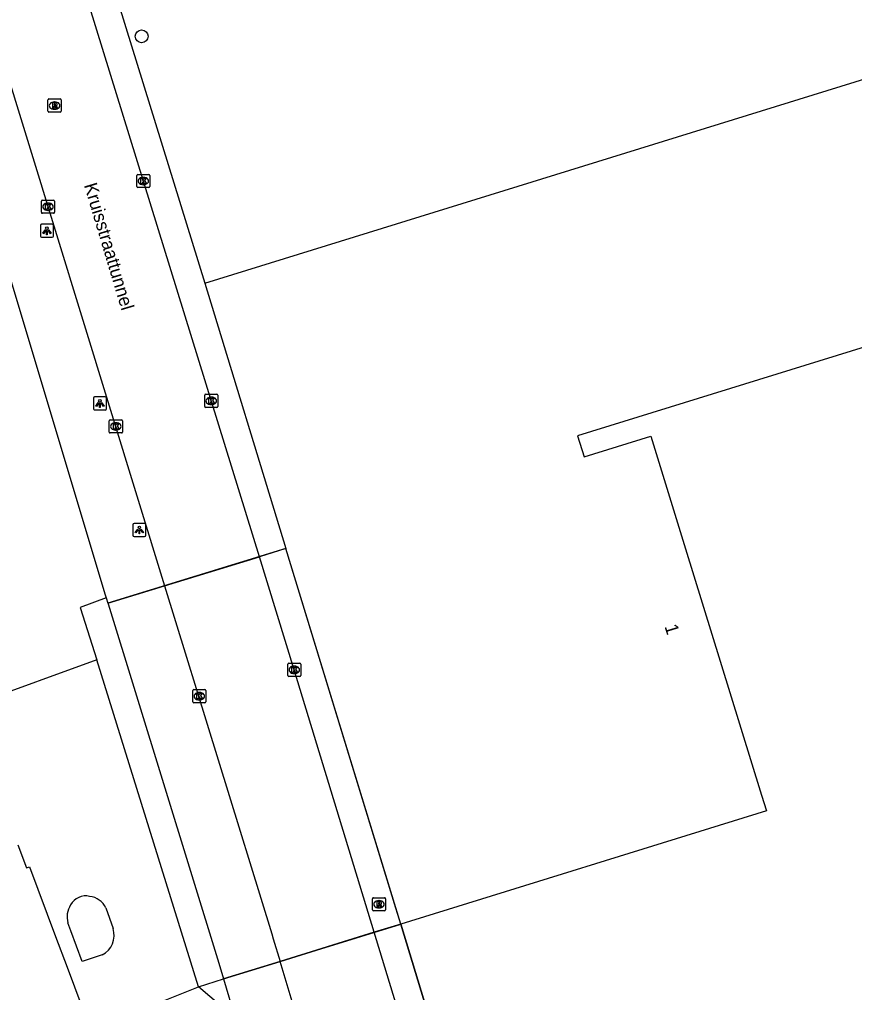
# Model space of a CAD drawing. Extents: x 160806 to 161707, y 383697 to 384148.
# Drawn here: x 161101 to 161164.6, y 383921.8 to 383995.8 of the extents above; entities that cross this region are included whole.
import ezdxf

# ---------------------------------------------------------------- set-up
doc = ezdxf.new("R2010")
doc.units = 0
for name, color, linetype in [('IMGEO_Boom', 7, 'Continuous'), ('IMGEO_Erf', 7, 'Continuous'), ('IMGEO_Fietspad_gesloten', 7, 'Continuous'), ('IMGEO_Kolk', 7, 'Continuous'), ('IMGEO_Lichtpunt', 7, 'Continuous'), ('IMGEO_Muur', 7, 'Continuous'), ('IMGEO_Openbare_ruimte_label', 7, 'Continuous'), ('IMGEO_Pand', 7, 'Continuous'), ('IMGEO_Pand_nummerreeks', 7, 'Continuous'), ('IMGEO_Pand_overbouw', 7, 'Continuous'), ('IMGEO_Rioolput', 7, 'Continuous'), ('IMGEO_Tunneldeel', 7, 'Continuous'), ('IMGEO_Voetpad_open', 7, 'Continuous')]:
    doc.layers.add(name, color=color, linetype=linetype)

msp = doc.modelspace()

# ---------------------------------------------------------------- linework, layer by layer
at = {"layer": 'IMGEO_Boom'}
msp.add_circle((161110.294, 383994.548), 0.489, dxfattribs=at)
at = {"layer": 'IMGEO_Erf'}
msp.add_lwpolyline([(161130.022, 383926.988), (161135.107, 383910.27)], dxfattribs=at)
at = {"layer": 'IMGEO_Fietspad_gesloten'}
for points in [[(161119.258, 383954.945), (161104.758, 384001.93), (161103.731, 384005.273), (161103.627, 384007.38)], [(161096.658, 384002.717), (161097.481, 384000.05), (161112.041, 383952.737)], [(161112.041, 383952.737), (161119.258, 383954.945)], [(161128.001, 383926.363), (161121.915, 383946.336), (161119.258, 383954.945)], [(161112.041, 383952.737), (161120.194, 383926.245), (161120.308, 383925.869), (161120.828, 383924.144)], [(161120.828, 383924.144), (161128.001, 383926.363)], [(161128.001, 383926.363), (161120.828, 383924.144)], [(161137.527, 383894.886), (161137.397, 383895.319), (161137.082, 383896.366), (161136.2, 383899.301), (161135.228, 383902.537), (161134.295, 383905.64), (161133.125, 383909.533), (161132.871, 383910.379), (161128.001, 383926.363)], [(161130.415, 383892.303), (161130.285, 383892.737), (161129.981, 383893.745), (161129.099, 383896.676), (161128.124, 383899.912), (161127.188, 383903.021), (161124.879, 383910.69), (161120.828, 383924.144)]]:
    msp.add_lwpolyline(points, dxfattribs=at)
at = {"layer": 'IMGEO_Kolk'}
for p, q in [((161109.919, 383983.109), (161109.919, 383983.961)), ((161109.994, 383984.035), (161110.846, 383984.035)), ((161110.407, 383983.815), (161110.432, 383983.815)), ((161110.92, 383983.961), (161110.92, 383983.109)), ((161110.846, 383983.035), (161109.994, 383983.035)), ((161110.43, 383983.255), (161110.405, 383983.255)), ((161102.662, 383981.155), (161102.662, 383982.007)), ((161102.737, 383982.081), (161103.589, 383982.081)), ((161103.15, 383981.861), (161103.175, 383981.861)), ((161103.663, 383982.007), (161103.663, 383981.155)), ((161103.589, 383981.081), (161102.737, 383981.081)), ((161103.173, 383981.301), (161103.148, 383981.301)), ((161115.168, 383967.306), (161116.02, 383967.306)), ((161115.093, 383966.38), (161115.093, 383967.232)), ((161115.581, 383967.086), (161115.606, 383967.086)), ((161116.094, 383967.232), (161116.094, 383966.38)), ((161116.02, 383966.306), (161115.168, 383966.306)), ((161115.604, 383966.526), (161115.579, 383966.526)), ((161107.828, 383964.435), (161107.828, 383965.287)), ((161107.903, 383965.361), (161108.755, 383965.361)), ((161108.316, 383965.141), (161108.341, 383965.141)), ((161108.829, 383965.287), (161108.829, 383964.435)), ((161108.755, 383964.361), (161107.903, 383964.361)), ((161108.339, 383964.581), (161108.314, 383964.581)), ((161121.414, 383945.91), (161121.414, 383946.762)), ((161121.489, 383946.836), (161122.341, 383946.836)), ((161121.902, 383946.616), (161121.927, 383946.616)), ((161122.415, 383946.762), (161122.415, 383945.91)), ((161122.341, 383945.836), (161121.489, 383945.836)), ((161121.925, 383946.056), (161121.9, 383946.056)), ((161114.183, 383943.904), (161114.183, 383944.756)), ((161114.258, 383944.83), (161115.11, 383944.83)), ((161114.671, 383944.61), (161114.696, 383944.61)), ((161115.184, 383944.756), (161115.184, 383943.904)), ((161115.11, 383943.83), (161114.258, 383943.83)), ((161114.694, 383944.05), (161114.669, 383944.05))]:
    msp.add_line(p, q, dxfattribs=at)
for points in [[(161109.919, 383983.109), (161109.919, 383983.961)], [(161109.994, 383984.035), (161110.846, 383984.035)], [(161110.24, 383983.735), (161110.363, 383983.735), (161110.363, 383983.584), (161110.493, 383983.735), (161110.657, 383983.735), (161110.511, 383983.584), (161110.664, 383983.335), (161110.512, 383983.335), (161110.427, 383983.499), (161110.363, 383983.432), (161110.363, 383983.335), (161110.24, 383983.335), (161110.24, 383983.735)], [(161110.92, 383983.961), (161110.92, 383983.109)], [(161110.846, 383983.035), (161109.994, 383983.035)], [(161102.662, 383981.155), (161102.662, 383982.007)], [(161102.737, 383982.081), (161103.589, 383982.081)], [(161102.983, 383981.781), (161103.106, 383981.781), (161103.106, 383981.63), (161103.236, 383981.781), (161103.4, 383981.781), (161103.254, 383981.63), (161103.407, 383981.381), (161103.255, 383981.381), (161103.17, 383981.545), (161103.106, 383981.478), (161103.106, 383981.381), (161102.983, 383981.381), (161102.983, 383981.781)], [(161103.663, 383982.007), (161103.663, 383981.155)], [(161103.589, 383981.081), (161102.737, 383981.081)], [(161115.168, 383967.306), (161116.02, 383967.306)], [(161115.093, 383966.38), (161115.093, 383967.232)], [(161115.414, 383967.006), (161115.537, 383967.006), (161115.537, 383966.855), (161115.667, 383967.006), (161115.831, 383967.006), (161115.685, 383966.855), (161115.838, 383966.606), (161115.686, 383966.606), (161115.601, 383966.77), (161115.537, 383966.703), (161115.537, 383966.606), (161115.414, 383966.606), (161115.414, 383967.006)], [(161116.094, 383967.232), (161116.094, 383966.38)], [(161116.02, 383966.306), (161115.168, 383966.306)], [(161107.828, 383964.435), (161107.828, 383965.287)], [(161107.903, 383965.361), (161108.755, 383965.361)], [(161108.149, 383965.061), (161108.272, 383965.061), (161108.272, 383964.91), (161108.402, 383965.061), (161108.566, 383965.061), (161108.42, 383964.91), (161108.573, 383964.661), (161108.421, 383964.661), (161108.336, 383964.825), (161108.272, 383964.758), (161108.272, 383964.661), (161108.149, 383964.661), (161108.149, 383965.061)], [(161108.829, 383965.287), (161108.829, 383964.435)], [(161108.755, 383964.361), (161107.903, 383964.361)], [(161121.414, 383945.91), (161121.414, 383946.762)], [(161121.489, 383946.836), (161122.341, 383946.836)], [(161122.415, 383946.762), (161122.415, 383945.91)], [(161122.341, 383945.836), (161121.489, 383945.836)], [(161121.735, 383946.536), (161121.858, 383946.536), (161121.858, 383946.385), (161121.988, 383946.536), (161122.152, 383946.536), (161122.006, 383946.385), (161122.159, 383946.136), (161122.007, 383946.136), (161121.922, 383946.3), (161121.858, 383946.233), (161121.858, 383946.136), (161121.735, 383946.136), (161121.735, 383946.536)], [(161114.183, 383943.904), (161114.183, 383944.756)], [(161114.258, 383944.83), (161115.11, 383944.83)], [(161114.504, 383944.53), (161114.627, 383944.53), (161114.627, 383944.379), (161114.757, 383944.53), (161114.921, 383944.53), (161114.775, 383944.379), (161114.928, 383944.13), (161114.776, 383944.13), (161114.691, 383944.294), (161114.627, 383944.227), (161114.627, 383944.13), (161114.504, 383944.13), (161114.504, 383944.53)], [(161115.184, 383944.756), (161115.184, 383943.904)], [(161115.11, 383943.83), (161114.258, 383943.83)]]:
    msp.add_lwpolyline(points, dxfattribs=at)
for centre, start, end in [((161109.996, 383983.959), 91.55205, 178.44795), ((161109.996, 383983.959), 91.55205, 178.44795), ((161110.844, 383983.959), 1.55205, 88.44795), ((161110.844, 383983.959), 1.55205, 88.44795), ((161109.996, 383983.111), 181.55205, 268.44795), ((161109.996, 383983.111), 181.55205, 268.44795), ((161110.844, 383983.111), 271.55205, 358.44795), ((161110.844, 383983.111), 271.55205, 358.44795), ((161102.739, 383982.005), 91.55205, 178.44795), ((161102.739, 383982.005), 91.55205, 178.44795), ((161103.587, 383982.005), 1.55205, 88.44795), ((161103.587, 383982.005), 1.55205, 88.44795), ((161102.739, 383981.157), 181.55205, 268.44795), ((161102.739, 383981.157), 181.55205, 268.44795), ((161103.587, 383981.157), 271.55205, 358.44795), ((161103.587, 383981.157), 271.55205, 358.44795), ((161115.17, 383967.23), 91.55205, 178.44795), ((161115.17, 383967.23), 91.55205, 178.44795), ((161116.018, 383967.23), 1.55205, 88.44795), ((161116.018, 383967.23), 1.55205, 88.44795), ((161115.17, 383966.382), 181.55205, 268.44795), ((161115.17, 383966.382), 181.55205, 268.44795), ((161116.018, 383966.382), 271.55205, 358.44795), ((161116.018, 383966.382), 271.55205, 358.44795), ((161107.905, 383965.285), 91.55205, 178.44795), ((161107.905, 383965.285), 91.55205, 178.44795), ((161108.753, 383965.285), 1.55205, 88.44795), ((161108.753, 383965.285), 1.55205, 88.44795), ((161107.905, 383964.437), 181.55205, 268.44795), ((161107.905, 383964.437), 181.55205, 268.44795), ((161108.753, 383964.437), 271.55205, 358.44795), ((161108.753, 383964.437), 271.55205, 358.44795), ((161121.491, 383946.76), 91.55205, 178.44795), ((161121.491, 383946.76), 91.55205, 178.44795), ((161122.339, 383946.76), 1.55205, 88.44795), ((161122.339, 383946.76), 1.55205, 88.44795), ((161121.491, 383945.912), 181.55205, 268.44795), ((161121.491, 383945.912), 181.55205, 268.44795), ((161122.339, 383945.912), 271.55205, 358.44795), ((161122.339, 383945.912), 271.55205, 358.44795), ((161114.26, 383944.754), 91.55205, 178.44795), ((161114.26, 383944.754), 91.55205, 178.44795), ((161115.108, 383944.754), 1.55205, 88.44795), ((161115.108, 383944.754), 1.55205, 88.44795), ((161114.26, 383943.906), 181.55205, 268.44795), ((161114.26, 383943.906), 181.55205, 268.44795), ((161115.108, 383943.906), 271.55205, 358.44795), ((161115.108, 383943.906), 271.55205, 358.44795)]:
    msp.add_arc(centre, 0.0765, start, end, dxfattribs=at)
for centre, major_axis, ratio, start_param, end_param in [((161110.406, 383983.535), (-0.387, 0.002), 0.722429, 4.712389, 7.853982), ((161110.431, 383983.535), (-0.39, 0.002), 0.717154, 1.570796, 4.712389), ((161103.149, 383981.581), (-0.387, 0.002), 0.722429, 4.712389, 7.853982), ((161103.174, 383981.581), (-0.39, 0.002), 0.717154, 1.570796, 4.712389), ((161115.58, 383966.806), (-0.387, 0.002), 0.722429, 4.712389, 7.853982), ((161115.605, 383966.806), (-0.39, 0.002), 0.717154, 1.570796, 4.712389), ((161108.315, 383964.861), (-0.387, 0.002), 0.722429, 4.712389, 7.853982), ((161108.34, 383964.861), (-0.39, 0.002), 0.717154, 1.570796, 4.712389), ((161121.901, 383946.336), (-0.387, 0.002), 0.722429, 4.712389, 7.853982), ((161121.926, 383946.336), (-0.39, 0.002), 0.717154, 1.570796, 4.712389), ((161114.67, 383944.33), (-0.387, 0.002), 0.722429, 4.712389, 7.853982), ((161114.695, 383944.33), (-0.39, 0.002), 0.717154, 1.570796, 4.712389)]:
    msp.add_ellipse(centre, major_axis=major_axis, ratio=ratio, start_param=start_param, end_param=end_param, dxfattribs=at)
at = {"layer": 'IMGEO_Lichtpunt'}
for p, q in [((161102.588, 383980.156), (161102.588, 383979.349)), ((161102.588, 383980.156), (161102.588, 383979.349)), ((161103.49, 383980.251), (161102.682, 383980.251)), ((161103.49, 383980.251), (161102.682, 383980.251)), ((161103.584, 383979.349), (161103.584, 383980.156)), ((161103.584, 383979.349), (161103.584, 383980.156)), ((161102.682, 383979.255), (161103.49, 383979.255)), ((161102.682, 383979.255), (161103.49, 383979.255)), ((161106.623, 383967.012), (161106.623, 383966.205)), ((161106.623, 383967.012), (161106.623, 383966.205)), ((161107.525, 383967.107), (161106.717, 383967.107)), ((161107.525, 383967.107), (161106.717, 383967.107)), ((161107.619, 383966.205), (161107.619, 383967.012)), ((161107.619, 383966.205), (161107.619, 383967.012)), ((161106.717, 383966.111), (161107.525, 383966.111)), ((161106.717, 383966.111), (161107.525, 383966.111)), ((161109.621, 383957.381), (161109.621, 383956.574)), ((161109.621, 383957.381), (161109.621, 383956.574)), ((161110.523, 383957.476), (161109.715, 383957.476)), ((161110.523, 383957.476), (161109.715, 383957.476)), ((161110.617, 383956.574), (161110.617, 383957.381)), ((161110.617, 383956.574), (161110.617, 383957.381)), ((161109.715, 383956.48), (161110.523, 383956.48)), ((161109.715, 383956.48), (161110.523, 383956.48))]:
    msp.add_line(p, q, dxfattribs=at)
for points in [[(161102.962, 383979.82), (161103.001, 383979.792), (161102.813, 383979.53), (161102.775, 383979.557), (161102.962, 383979.82)], [(161103.064, 383979.772), (161103.111, 383979.772), (161103.111, 383979.45), (161103.064, 383979.45), (161103.064, 383979.772)], [(161103.174, 383979.792), (161103.212, 383979.819), (161103.399, 383979.557), (161103.36, 383979.529), (161103.174, 383979.792)], [(161106.997, 383966.676), (161107.036, 383966.648), (161106.848, 383966.386), (161106.81, 383966.413), (161106.997, 383966.676)], [(161107.099, 383966.628), (161107.146, 383966.628), (161107.146, 383966.306), (161107.099, 383966.306), (161107.099, 383966.628)], [(161107.209, 383966.648), (161107.247, 383966.675), (161107.434, 383966.413), (161107.395, 383966.385), (161107.209, 383966.648)], [(161109.995, 383957.045), (161110.034, 383957.017), (161109.846, 383956.755), (161109.808, 383956.782), (161109.995, 383957.045)], [(161110.097, 383956.997), (161110.144, 383956.997), (161110.144, 383956.675), (161110.097, 383956.675), (161110.097, 383956.997)], [(161110.207, 383957.017), (161110.245, 383957.044), (161110.432, 383956.782), (161110.393, 383956.754), (161110.207, 383957.017)]]:
    msp.add_lwpolyline(points, dxfattribs=at)
for centre in [(161103.087, 383979.954), (161107.122, 383966.81), (161110.12, 383957.179)]:
    msp.add_circle(centre, 0.0994, dxfattribs=at)
for centre, start, end in [((161102.682, 383980.156), 90, 180), ((161102.682, 383980.156), 90, 180), ((161103.49, 383980.156), 0, 90), ((161103.49, 383980.156), 0, 90), ((161102.682, 383979.349), 180, 270), ((161102.682, 383979.349), 180, 270), ((161103.49, 383979.349), 270, 0), ((161103.49, 383979.349), 270, 360), ((161106.717, 383967.012), 90, 180), ((161106.717, 383967.012), 90, 180), ((161107.525, 383967.012), 0, 90), ((161107.525, 383967.012), 0, 90), ((161106.717, 383966.205), 180, 270), ((161106.717, 383966.205), 180, 270), ((161107.525, 383966.205), 270, 0), ((161107.525, 383966.205), 270, 360), ((161109.715, 383957.381), 90, 180), ((161109.715, 383957.381), 90, 180), ((161110.523, 383957.381), 0, 90), ((161110.523, 383957.381), 0, 90), ((161109.715, 383956.574), 180, 270), ((161109.715, 383956.574), 180, 270), ((161110.523, 383956.574), 270, 0), ((161110.523, 383956.574), 270, 360)]:
    msp.add_arc(centre, 0.0946, start, end, dxfattribs=at)
at = {"layer": 'IMGEO_Muur'}
msp.add_lwpolyline([(161107.16, 384001.487), (161115.101, 383975.756)], dxfattribs=at)
at = {"layer": 'IMGEO_Pand'}
for points in [[(161115.101, 383975.756), (161174.941, 383994.27), (161177.371, 383986.415), (161171.512, 383984.603), (161172.182, 383982.438), (161174.353, 383983.11), (161177.012, 383974.513), (161143.485, 383964.14), (161143.98, 383962.542), (161149.045, 383964.109), (161151.693, 383955.552), (161154.338, 383947.003), (161157.491, 383936.811), (161157.865, 383935.602), (161130.022, 383926.988)], [(161100.111, 383976.738), (161107.531, 383952.042), (161107.6, 383951.813)], [(161115.101, 383975.756), (161121.28, 383955.564)], [(161106.884, 383947.107), (161097.811, 383943.794), (161096.394, 383947.689), (161093.935, 383946.784), (161089.243, 383959.541), (161088.989, 383960.21), (161089.4, 383960.366), (161088.341, 383960.814), (161085.868, 383967.537), (161088.671, 383968.566), (161088.381, 383969.366), (161088.121, 383972.173), (161083.322, 383970.394), (161082.015, 383971.009), (161080.801, 383974.286), (161078.917, 383973.592), (161080.52, 383969.246), (161079.25, 383966.494), (161061.198, 383959.507), (161058.517, 383960.756), (161055.383, 383959.639), (161052.414, 383967.479), (161050.66, 383972.267), (161051.661, 383972.634)], [(161130.022, 383926.988), (161129.654, 383928.199), (161121.28, 383955.564)], [(161107.6, 383951.813), (161105.62, 383951.085), (161106.884, 383947.107)], [(161107.6, 383951.813), (161107.72, 383951.415)], [(161107.72, 383951.415), (161107.738, 383951.357), (161116.164, 383924.025), (161116.526, 383922.813)], [(161114.626, 383922.225), (161106.884, 383947.107)], [(161100.88, 383933.031), (161101.538, 383931.265), (161101.771, 383931.352), (161103.75, 383926.041), (161104.623, 383923.698), (161106.369, 383919.012)], [(161107.57, 383928.223), (161108.122, 383926.651)], [(161104.896, 383926.475), (161104.676, 383927.072)], [(161107.3, 383924.64), (161105.758, 383924.128), (161104.896, 383926.475)], [(161114.626, 383922.225), (161116.526, 383922.813)]]:
    msp.add_lwpolyline(points, dxfattribs=at)
for centre, radius, start, end in [((161106.032, 383927.834), 1.297, 76.3862, 151.90489), ((161106.165, 383927.544), 1.561, 25.80334, 83.65938), ((161106.351, 383927.517), 1.733, 147.63928, 194.88722), ((161106.521, 383926.132), 1.683, 297.56088, 17.97436)]:
    msp.add_arc(centre, radius, start, end, dxfattribs=at)
at = {"layer": 'IMGEO_Pand_overbouw'}
msp.add_lwpolyline([(161121.28, 383955.564), (161107.72, 383951.415), (161107.738, 383951.357), (161116.164, 383924.025), (161116.526, 383922.813), (161130.022, 383926.988)], close=True, dxfattribs=at)
at = {"layer": 'IMGEO_Rioolput'}
for p, q in [((161103.167, 383988.853), (161103.167, 383989.705)), ((161103.242, 383989.779), (161104.094, 383989.779)), ((161103.655, 383989.559), (161103.68, 383989.559)), ((161104.168, 383989.705), (161104.168, 383988.853)), ((161104.094, 383988.779), (161103.242, 383988.779)), ((161103.678, 383988.999), (161103.653, 383988.999)), ((161127.859, 383928.07), (161127.859, 383928.922)), ((161127.934, 383928.996), (161128.786, 383928.996)), ((161128.347, 383928.776), (161128.372, 383928.776)), ((161128.86, 383928.922), (161128.86, 383928.07)), ((161128.37, 383928.216), (161128.345, 383928.216)), ((161128.786, 383927.996), (161127.934, 383927.996))]:
    msp.add_line(p, q, dxfattribs=at)
for points in [[(161103.167, 383988.853), (161103.167, 383989.705)], [(161103.242, 383989.779), (161104.094, 383989.779)], [(161104.168, 383989.705), (161104.168, 383988.853)], [(161104.094, 383988.779), (161103.242, 383988.779)], [(161103.756, 383989.477), (161103.504, 383989.479), (161103.504, 383989.079)], [(161103.504, 383989.079), (161103.628, 383989.079), (161103.628, 383989.241), (161103.639, 383989.241)], [(161103.682, 383989.398), (161103.628, 383989.398), (161103.628, 383989.317)], [(161103.628, 383989.317), (161103.68, 383989.317)], [(161103.686, 383989.212), (161103.757, 383989.079), (161103.897, 383989.079), (161103.832, 383989.205)], [(161127.859, 383928.07), (161127.859, 383928.922)], [(161127.934, 383928.996), (161128.786, 383928.996)], [(161128.86, 383928.922), (161128.86, 383928.07)], [(161128.448, 383928.694), (161128.196, 383928.696), (161128.196, 383928.296)], [(161128.196, 383928.296), (161128.32, 383928.296), (161128.32, 383928.458), (161128.331, 383928.458)], [(161128.374, 383928.615), (161128.32, 383928.615), (161128.32, 383928.534)], [(161128.32, 383928.534), (161128.372, 383928.534)], [(161128.378, 383928.429), (161128.449, 383928.296), (161128.589, 383928.296), (161128.524, 383928.422)], [(161128.786, 383927.996), (161127.934, 383927.996)]]:
    msp.add_lwpolyline(points, dxfattribs=at)
for centre, radius, start, end in [((161103.244, 383989.703), 0.0765, 91.55205, 178.44795), ((161103.244, 383989.703), 0.0765, 91.55205, 178.44795), ((161104.092, 383989.703), 0.0765, 1.55205, 88.44795), ((161104.092, 383989.703), 0.0765, 1.55205, 88.44795), ((161103.244, 383988.855), 0.0765, 181.55205, 268.44795), ((161103.244, 383988.855), 0.0765, 181.55205, 268.44795), ((161103.638, 383989.188), 0.0533, 26.02933, 88.69889), ((161103.664, 383989.506), 0.19, 274.7715, 282.96867), ((161103.688, 383989.302), 0.0964, 77.00612, 93.18647), ((161103.702, 383989.359), 0.0378, 276.66336, 79.67722), ((161103.755, 383989.367), 0.109, 350.36119, 89.41601), ((161103.753, 383989.367), 0.112, 277.58423, 350.98172), ((161103.737, 383989.152), 0.108, 29.51342, 73.79051), ((161104.092, 383988.855), 0.0765, 271.55205, 358.44795), ((161104.092, 383988.855), 0.0765, 271.55205, 358.44795), ((161127.936, 383928.92), 0.0765, 91.55205, 178.44795), ((161127.936, 383928.92), 0.0765, 91.55205, 178.44795), ((161128.784, 383928.92), 0.0765, 1.55205, 88.44795), ((161128.784, 383928.92), 0.0765, 1.55205, 88.44795), ((161127.936, 383928.072), 0.0765, 181.55205, 268.44795), ((161127.936, 383928.072), 0.0765, 181.55205, 268.44795), ((161128.33, 383928.405), 0.0533, 26.02933, 88.69889), ((161128.356, 383928.723), 0.19, 274.7715, 282.96867), ((161128.38, 383928.519), 0.0964, 77.00612, 93.18647), ((161128.394, 383928.576), 0.0378, 276.66336, 79.67722), ((161128.447, 383928.584), 0.109, 350.36119, 89.41601), ((161128.445, 383928.584), 0.112, 277.58423, 350.98172), ((161128.429, 383928.369), 0.108, 29.51342, 73.79051), ((161128.784, 383928.072), 0.0765, 271.55205, 358.44795), ((161128.784, 383928.072), 0.0765, 271.55205, 358.44795)]:
    msp.add_arc(centre, radius, start, end, dxfattribs=at)
for centre, major_axis, ratio, start_param, end_param in [((161103.654, 383989.279), (-0.387, 0.002), 0.722429, 4.712389, 7.853982), ((161103.679, 383989.279), (-0.39, 0.002), 0.717154, 1.570796, 4.712389), ((161128.346, 383928.496), (-0.387, 0.002), 0.722429, 4.712389, 7.853982), ((161128.371, 383928.496), (-0.39, 0.002), 0.717154, 1.570796, 4.712389)]:
    msp.add_ellipse(centre, major_axis=major_axis, ratio=ratio, start_param=start_param, end_param=end_param, dxfattribs=at)
at = {"layer": 'IMGEO_Tunneldeel'}
msp.add_lwpolyline([(161136.395, 383906.417), (161135.107, 383910.27), (161130.022, 383926.988), (161128.001, 383926.363), (161120.828, 383924.144), (161116.526, 383922.813), (161117.416, 383919.839), (161118.837, 383915.091), (161120.497, 383909.633), (161121.279, 383907.023), (161121.435, 383906.506), (161122.947, 383901.461), (161125.73, 383892.176), (161126.025, 383891.192), (161126.095, 383890.959), (161125.939, 383890.924), (161126.007, 383890.701), (161130.415, 383892.303), (161137.527, 383894.886), (161139.721, 383895.683), (161139.661, 383895.886), (161139.496, 383895.835), (161139.429, 383896.055), (161139.108, 383897.114)], close=True, dxfattribs=at)
at = {"layer": 'IMGEO_Voetpad_open'}
for points in [[(161107.408, 384024.109), (161106.928, 384021.186), (161106.784, 384020.283), (161105.349, 384011.638), (161106.437, 384005.758), (161105.911, 384005.605), (161107.16, 384001.487), (161115.101, 383975.756)], [(161121.28, 383955.564), (161119.258, 383954.945)], [(161107.72, 383951.415), (161112.041, 383952.737)], [(161128.001, 383926.363), (161130.022, 383926.988)], [(161137.527, 383894.886), (161139.721, 383895.683), (161139.661, 383895.886), (161139.496, 383895.835), (161139.429, 383896.055), (161139.108, 383897.114), (161136.395, 383906.417), (161135.107, 383910.27), (161130.022, 383926.988), (161128.001, 383926.363)], [(161116.526, 383922.813), (161120.828, 383924.144)], [(161120.828, 383924.144), (161116.526, 383922.813), (161117.416, 383919.839), (161118.837, 383915.091), (161120.497, 383909.633), (161121.279, 383907.023), (161121.435, 383906.506), (161122.947, 383901.461), (161125.73, 383892.176), (161126.025, 383891.192), (161126.095, 383890.959), (161125.939, 383890.924), (161126.007, 383890.701), (161130.415, 383892.303)], [(161056.247, 383885.258), (161085.633, 383896.162), (161086.368, 383895.852), (161097.15, 383899.812), (161099.69, 383905.487), (161096.881, 383913.365), (161111.083, 383918.654), (161110.447, 383920.534), (161114.626, 383922.225)], [(161117.416, 383919.839), (161117.213, 383920.012), (161114.626, 383922.225)], [(161116.526, 383922.813), (161117.416, 383919.839)]]:
    msp.add_lwpolyline(points, dxfattribs=at)

# ---------------------------------------------------------------- texts
at = {"layer": 'IMGEO_Openbare_ruimte_label'}
msp.add_text('Kruisstraattunnel', height=1, rotation=286.67729, dxfattribs=at).set_placement((161105.897, 383983.228))
at = {"layer": 'IMGEO_Pand_nummerreeks'}
msp.add_text('1', height=1, rotation=287.19206, dxfattribs=at).set_placement((161150.087, 383949.645))

doc.saveas('drawing.dxf')
